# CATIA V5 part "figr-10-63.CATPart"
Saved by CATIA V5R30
Part number: Part3
Bounding box of the stored display mesh (mm): x -76.186 to 89.68, y -206 to 106, z -21.666 to 136.547
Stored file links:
  D:\PROJECTS\CATIA V56R 2020\Resources\Parts File\c10_catia_v5_6r2020_prt\figr-10-63.CATPart
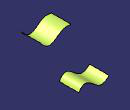
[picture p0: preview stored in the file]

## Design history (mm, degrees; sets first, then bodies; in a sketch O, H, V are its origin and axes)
Set1
  Plane1: type Offset, RefPlane zx-plane, Offset 100, reversed
  Sketch1 on Plane1, origin (0, -100, 0), H (-1, 0, 0), V (0, 0, 1)
    spline S1 through (-89.6797, 128.7958) (-21.8257, 98.6681) (14.6145, 123.4397) (76.1857, 133.4823)
  Extrude1: Element1 Sketch2, Lim1 106, Lim2 0, Direction zx-plane
  Extrude2: Element1 Sketch1, Lim1 106, Lim2 0, Direction Plane1
Body1 (main body)
  Sketch2 on zx-plane, origin (0, 0, 0), H (-1, 0, 0), V (0, 0, 1)
    spline S1 through (-88.2413, 0) (-57.9275, 26.3209) (-11.5211, 3.1904) (32.6399, -21.5353) (74.1811, 0)
    point P1 (-88.2413, 0)
    point P2 (74.1811, 0)
    coincidence: P1 H, P2 H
